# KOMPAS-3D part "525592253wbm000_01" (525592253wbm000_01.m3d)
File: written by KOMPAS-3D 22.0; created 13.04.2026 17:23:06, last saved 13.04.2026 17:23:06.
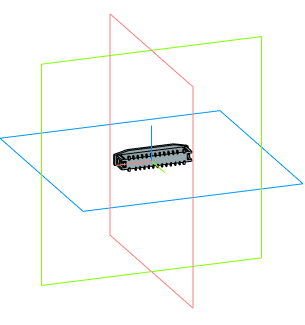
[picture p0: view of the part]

Document properties: Автор: Andrey; Полное имя файла: C:\Users\User1\Documents\525592253wbm000_01.m3d

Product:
- Part/product: 525592253wbm000_01

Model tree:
1. Операция без истории:1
